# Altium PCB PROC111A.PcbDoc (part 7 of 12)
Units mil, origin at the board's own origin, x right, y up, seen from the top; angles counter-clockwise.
Board outline 7700 x 2300 mil, 6 copper layers (Top Layer, GND 1, SIG 1, SIG 2, GND 2, Bottom Layer), stack 61.062 mil thick; 841 components, 632 nets, 2914 pads, 1627 vias.
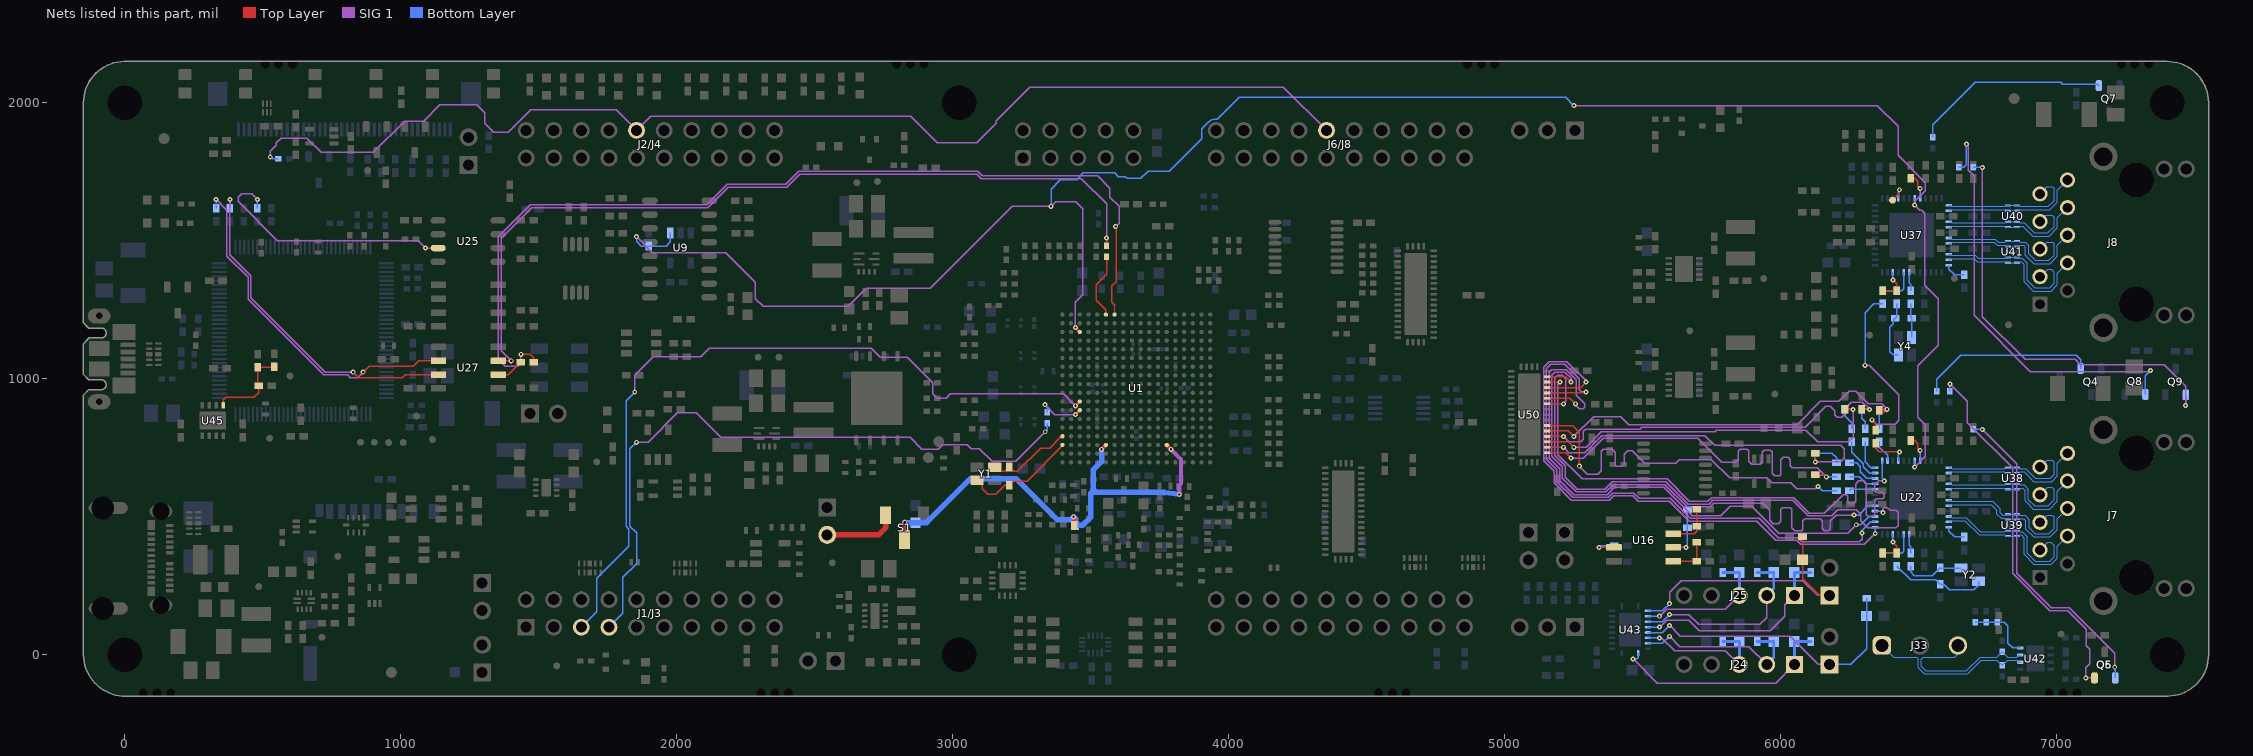
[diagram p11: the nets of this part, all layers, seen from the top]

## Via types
v1: diameter 18, hole 8, Top Layer to Bottom Layer, tented both sides, 1523 vias
v2: diameter 19.68, hole 7.87, Top Layer to Bottom Layer, tented both sides, 104 vias

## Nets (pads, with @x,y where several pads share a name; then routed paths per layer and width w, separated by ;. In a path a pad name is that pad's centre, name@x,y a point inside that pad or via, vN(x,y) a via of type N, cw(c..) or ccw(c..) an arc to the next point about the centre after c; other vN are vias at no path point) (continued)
AM263_TMS_XDS: R134.1 U25.3 | length 925.6
  Top Layer w5.3: v1(1090,1473.86) U25.3@1135.36,1473.86
  SIG 1 w4.75: v1(480.73,1650) 460.73,1670 423.12,1670 410.7,1657.58 410.7,1642.42 553.12,1500 1063.86,1500 v1(1090,1473.86)
  Bottom Layer w5.3: R134.1@480.5,1617.63 480.5,1649.77 v1(480.73,1650)
AM263_UART0_RXD: R327.1 U1.A7 | length 3465.7
  Top Layer w4: U1.A7@3586.11,1232.8 3586.11,1264.29
  Top Layer w5.3: v1(1435,1088.85) 1468.09,1088.85 1481.5,1075.45 R327.1@1481.5,1060 ; 3586.11,1264.29 3586.11,1266.7 3576.25,1276.56 3576.25,1336.51 3592.03,1352.29 3592.03,1549.64 v1(3590.08,1551.6)
  SIG 1 w4.75: v1(1435,1088.85) 1435,1057.95 1423.07,1046.02 1379.25,1046.02 1353.89,1071.38 1353.89,1514.49 1469.11,1629.71 2107.66,1629.71 2182.56,1704.61 2394.64,1704.61 2442.05,1752.02 3090.56,1752.02 3107.48,1735.1 3525.32,1735.1 3569.24,1691.18 3569.24,1658.21 3602.39,1625.06 3602.39,1563.91 v1(3590.08,1551.6)
AM263_UART0_RXD_R: R327.2 U27.2 | length 99.5
  Top Layer w5.3: U27.2@1353.27,1015.27 1389.52,1015.27 R327.2@1434.25,1060
AM263_UART0_RXD_XDS: R131.1 U27.7 | length 1225
  Top Layer w5.3: v1(827.49,1023.93) 847.33,1004.09 1005,1004.09 ; 1005,1004.4 1005.32,1004.4 1016.18,1015.27 U27.7@1136.73,1015.27
  SIG 1 w4.75: v1(380.73,1650) 380.73,1448.86 457.1,1372.49 457.1,1292.9 726.07,1023.93 v1(827.49,1023.93)
  Bottom Layer w5.3: R131.1@380.5,1617.63 380.5,1649.77 v1(380.73,1650)
AM263_UART0_TXD: R164.1 U27.3 | length 2991.7
  Top Layer w5.3: U27.3@1353.27,1065.27 v1(1400,1065.27) ; R164.1@3557,1482.17 v1(3557,1510.23)
  SIG 1 w4.75: v1(1400,1065.27) 1363.94,1101.33 1363.94,1508.94 1474.66,1619.66 2111.82,1619.66 2186.72,1694.56 2398.8,1694.56 2446.21,1741.97 3086.4,1741.97 3103.32,1725.05 3466.28,1725.05 3557,1634.33 v1(3557,1510.23)
AM263_UART0_TXD_R: R164.2 U1.A6 | length 241.4
  Top Layer w5.3: U1.A6@3554.61,1232.8 3554.61,1250.18 3519.34,1285.45 3519.34,1340.02 3558.39,1379.07 3558.39,1441.41 R164.2@3557,1442.8
AM263_UART0_TXD_XDS: R129.1 U27.6 | length 1275
  Top Layer w5.3: v1(863.7,1023.93) 885.48,1045.71 1045.71,1045.71 1065.27,1065.27 U27.6@1136.73,1065.27
  SIG 1 w4.75: v1(330.73,1650) 370.13,1610.6 370.13,1444.47 446.5,1368.1 446.5,1288.51 720.55,1014.46 721.33,1014.46 721.91,1013.88 807.81,1013.88 817.28,1004.41 844.18,1004.41 v1(863.7,1023.93)
  Bottom Layer w5.3: R129.1@330.5,1617.63 330.5,1649.77 v1(330.73,1650)
AM263_UART1_RXD: J1/J3.3 U1.L3 | length 2783.2
  Top Layer w10: v1(3444.38,902.09) U1.L3@3460.12,917.83
  SIG 1 w4.75: v1(1847.69,951.65) 1847.69,1012.66 1914.46,1079.44 2087.21,1079.44 2118.14,1110.36 2705.42,1110.36 2737.28,1078.5 2834.8,1078.5 2928.21,985.09 2928.21,945 2943.21,930 2975.39,930 2990.39,945 3401.46,945 v1(3444.38,902.09)
  Bottom Layer w5.3: J1/J3.3@1654.17,100 1710,155.83 1710,276.72 1826.8,393.51 1826.8,454.62 1816.24,465.18 1816.24,920.2 v1(1847.69,951.65)
AM263_UART1_TXD: J1/J3.4 R165.1 | length 2422
  SIG 1 w4.75: v1(1854.02,769.76) 1895.73,769.76 2002.38,876.42 2071.36,876.42 2159.83,787.95 2845.7,787.95 2888.23,745.42 2947.69,745.42 2963.32,761.06 3052.97,761.06 3066.83,747.2 3096.37,747.2 3142.87,700.7 3228.14,700.7 3255.31,727.88 3255.31,728.5 v1(3335,808.19)
  Bottom Layer w5.3: J1/J3.4@1754.17,100 1805,150.83 1805,281.22 1854.54,330.76 1854.54,441.87 1830.4,466.02 1830.4,746.14 v1(1854.02,769.76) ; v1@3335,807.6 3342.19,814.79 R165.1@3342.19,839.72
AM263_UART1_TXD_R: R165.2 U1.M3 | length 177.1
  Top Layer w10: v1(3444.38,870.59) U1.M3@3460.12,886.34
  SIG 1 w5.3: v1(3334.5,906.16) 3370.07,870.59 v1(3444.38,870.59)
  Bottom Layer w5.3: v1(3334.5,906.16) 3342.19,898.47 R165.2@3342.19,879.09
AM263_WARMRSTN: R5.2 U1.C3 U9.1 U22.43 U37.43 | length 7357.5
  Top Layer w10: v1(3444.38,1185.55) U1.C3@3460.12,1169.8
  SIG 1 w4.75: v1(1854.02,1515) 1911.65,1457.37 2177.48,1457.37 2285,1349.85 2285,1290.79 2313,1262.79 2620.94,1262.79 2685.96,1327.81 2919.1,1327.81 3216.29,1625 v1(3356.1,1625) 3372.16,1641.06 3446.17,1641.06 3470.22,1617 3470.22,1303.81 3444.38,1277.97 v1(3444.38,1185.55) ; v1(5250,1990) 6350,1990 6425,1915 6425,1810.02 6524.25,1710.77 6524.25,1682.03 6485.02,1642.8 v1(6485.02,1629.98) 6504,1611 6510.47,1611 6522.23,1599.23 6522.23,1338.26 6571.09,1289.41 6571.09,1121.92 6496.97,1047.79 6496.97,860.2 6524.25,832.92 6524.25,719.21 v1(6485.02,679.98)
  Bottom Layer w5.3: v1(1854.02,1515) 1854.02,1498.05 1871.02,1481.04 R5.2@1898.11,1481.04 1961.04,1481.04 1976.56,1496.56 U9.1@1976.56,1528.43 ; v1(3356.1,1625) 3356.1,1687.38 3390.1,1721.38 3448.34,1721.38 3472.81,1745.84 3586.02,1745.84 3598.95,1732.91 3624.33,1732.91 3631.32,1725.92 3681.74,1725.92 3707.48,1751.66 3784.31,1751.66 3902.21,1869.57 3902.21,1906.07 3927.45,1931.31 cw(c3954.19,1900.19) 3958.65,1940.98 4037.19,2019.52 5220.48,2019.52 v1(5250,1990) ; v1(6485.02,679.98) U22.43@6485.02,703.9 ; v1(6485.02,1629.98) U37.43@6485.02,1653.9
AM263_XTAL_XI: C58.1 U1.T1 Y1.1 | length 416.1
  Top Layer w5.3: Y1.1@3088.01,632.59 3092.89,632.59 3106.98,618.51 3106.98,601.63 3126.91,581.69 3155.48,581.69 3188.34,614.56 3204.72,614.56 C58.1@3205,614.84 3219.27,629.1 3269.37,629.1 3397.13,756.87 U1.T1@3397.13,760.35
AM263_XTAL_XO: C59.1 U1.R1 Y1.3 | length 317.9
  Top Layer w5.3: Y1.3@3151.99,679.84 3167.42,664.4 3188.69,664.4 C59.1@3205,680.71 3221.4,664.32 3233.73,664.32 3317.98,748.57 3350.62,748.57 3389.63,787.58 3392.86,787.58 U1.R1@3397.13,791.85
BP_PORZ: J2/J4.16 J6/J8.56 R180.2 | length 4341.6
  SIG 1 w4.75: v1(526.94,1803.36) 526.94,1824.32 549.25,1846.63 549.25,1855 566.59,1872.34 659.83,1872.34 711.41,1820.75 901.07,1820.75 1014.32,1934 1082.5,1934 1142,1993.5 1275,1993.5 1303.75,1964.75 1303.75,1926.75 1337.5,1893 1388.83,1893 1470,1974.17 1780,1974.17 J2/J4.16@1854.17,1900 1905.53,1951.36 2240,1951.36
  SIG 1 w5.3: 2240,1951.36 2847.77,1951.36 2944.28,1854.85 3087.63,1854.85 3158.06,1925.28 3158.06,1935.77 3279.01,2056.72 4197.45,2056.72 J6/J8.56@4354.17,1900
  Bottom Layer w5.3: v1(526.94,1803.36) 530.2,1803.36 536.24,1797.32 R180.2@556,1797.32
CAN_STB: R244.1 R248.1 R250.2 U42.8 | length 238
  Bottom Layer w5.3: R248.1@6705,117.87 R250.2@6745,117.87 R244.1@6785,117.87 6810,117.87 6823.16,104.71 6823.16,41.84 6840.16,24.84 U42.8@6867.68,24.84
CANA_N: J33.1 R246.2 U42.6 | length 601.7
  Bottom Layer w4.1: J33.1@6366.38,33.86 6409.77,-9.53 6492.64,-9.53 6498.72,-15.62 6498.72,-46.78 6520.48,-68.54 6676.84,-68.54 6726.39,-18.99 6783.25,-18.99 R246.2@6802.8,-38.54 6822.35,-18.99 6854.62,-18.99 6861.97,-26.34 U42.6@6867.68,-26.34
CANA_P: J33.3 R247.2 U42.7 | length 601.6
  Bottom Layer w4.1: J33.3@6641.97,33.86 6641.97,2.58 6629.86,-9.53 6516.4,-9.53 6509.62,-16.31 6509.62,-42.26 6525,-57.64 6672.33,-57.64 6721.87,-8.09 6783.25,-8.09 R247.2@6802.8,11.46 6822.35,-8.09 6854.62,-8.09 6861.97,-0.75 U42.7@6867.68,-0.75
DAC_EXT_VREF: J18.2 S1.3 | length 268.8
  Top Layer w20: J18.2@2545,434.47 2731.59,434.47 2756.71,459.58 S1.3@2756.71,506.22
DAC_VREF: C89.1 C90.1 C91.1 S1.2 U1.T6 U1.T13 | length 1749.6
  Top Layer w15: S1.2@2825.61,415.67 v1(2825.61,479.98) ; v1(3437.63,500) 3440,497.63 C91.1@3440,468.62 ; v1(3538.87,744.61) U1.T6@3554.61,760.35 ; U1.T13@3775.09,760.35 v1(3790.83,744.61)
  SIG 1 w15: v1(3790.83,744.61) 3827.15,708.29 3827.15,665.87 3827.15,620.15 3820.49,613.5 v1(3820.49,581.15)
  Bottom Layer w18: 3538.87,725.74 v1(3538.87,744.61)
  Bottom Layer w20: v1(2825.61,479.98) 2825.61,479.34 2826.45,478.5 C89.1@2865,478.5 2865,478.64 2905,478.64 3064.51,638.15 3229.55,638.15 3378.56,489.14 3426.78,489.14 v1(3437.63,500) 3445,492.63 C90.1@3445,468.53 3446.18,469.71 3470.8,469.71 3499.28,498.19 3499.28,584.65 3508.69,594.07 3508.69,669.75 3538.87,699.92 3538.87,725.74 ; 3503.16,588.54 3745.75,588.54 3765,588.18 cw(c3764.68,570.78) 3766.9,588.04 v1(3820.49,581.15)
EEPROM_A0: R318.2 R321.2 U16.1 | length 154.4
  Top Layer w5.3: U16.1@5610.08,339.14 5694.38,339.14 R318.2@5695.31,338.21 R321.2@5695.31,406.99
EEPROM_A1: R319.2 R322.2 U16.2 | length 184.1
  Top Layer w5.3: U16.2@5610.08,389.14 v1(5656.02,389.14)
  Bottom Layer w5.3: v1(5656.02,389.14) 5661.68,394.81 R322.2@5661.68,461.02 R319.2@5661.68,525
EEPROM_A2: R320.2 R323.2 U16.3 | length 167.7
  Top Layer w5.3: U16.3@5610.08,439.14 5686.53,439.14 5695.31,447.92 R323.2@5695.31,465 R320.2@5695.31,526.73
EEPROM_WP: R316.1 U16.7 | length 110.1
  Top Layer w5.3: v1(5342.11,389.14) U16.7@5395.51,389.14
  Bottom Layer w5.3: v1(5342.11,389.14) 5348.01,395.04 R316.1@5396.38,395.04
EQEP0_A: C214.1 J24.1 R236.1 U43.20 | length 828.4
  SIG 1 w4.75: v1(5465,-15) 5552.83,-102.83 5981.34,-102.83 J24.1@6049.18,-35
  Bottom Layer w5.3: v1(5465,-15) 5465.09,-14.91 5478.28,-14.91 5483.19,-10 U43.20@5483.19,5.98
  Bottom Layer w10: J24.1@6049.18,-35 C214.1@6049.18,48.5 R236.1@6109.18,48.5
EQEP0_B: C215.1 J24.2 R237.1 U43.18 | length 637.3
  SIG 1 w4.75: v1(5596.83,67) 5633.83,30 5884.18,30 J24.2@5949.18,-35
  Bottom Layer w5.3: U43.18@5518.62,41.41 5571.24,41.41 v1(5596.83,67)
  Bottom Layer w10: R237.1@5914.18,48.5 C215.1@5974.18,48.5 5974.18,-10 J24.2@5949.18,-35
EQEP0_INDEX: C216.1 J24.3 R238.1 U43.17 | length 514.2
  SIG 1 w4.75: v1(5560.83,61.1) 5563.26,58.67 5571.33,58.67 5615,15 5799.18,15 J24.3@5849.18,-35
  Bottom Layer w5.3: U43.17@5518.62,61.1 v1(5560.83,61.1)
  Bottom Layer w10: R238.1@5790,48.5 C216.1@5850,48.5 5850,-34.18 J24.3@5849.18,-35
EQEP0_STROBE: C220.1 J15.1 R242.1 U43.16 | length 1068.2
  SIG 1 w5.3: v1(5596.83,106.37) 5636.2,67 6034.58,67 6136.58,-35 J15.1@6177.06,-35
  Bottom Layer w5.3: U43.16@5518.62,80.78 5571.24,80.78 v1(5596.83,106.37) ; J15.1@6177.06,-35 6252.9,-35 6310.67,22.77 C220.1@6310.67,140.82 6311.51,141.66 R242.1@6311.51,205.53
EQEP2_A: C217.1 J25.1 R239.1 U43.15 | length 777.5
  SIG 1 w4.75: v1(5560.83,100.47) 5585.98,125.62 5666.23,125.62 5705,86.85 5961.85,86.85 6015,140 6015,180.82 J25.1@6049.18,215
  Bottom Layer w5.3: U43.15@5518.62,100.47 v1(5560.83,100.47)
  Bottom Layer w10: J25.1@6049.18,215 C217.1@6049.18,298.5 R239.1@6109.18,298.5
EQEP2_B: C218.1 J25.2 R240.1 U43.14 | length 700.2
  SIG 1 w4.75: v1(5596.83,145.74) 5666.12,145.74 5701.86,110 5924.18,110 5949.18,135 J25.2@5949.18,215
  Bottom Layer w5.3: U43.14@5518.62,120.15 5571.24,120.15 v1(5596.83,145.74)
  Bottom Layer w10: R240.1@5914.18,298.5 C218.1@5974.18,298.5 5974.18,240 J25.2@5949.18,215
EQEP2_INDEX: C219.1 J25.3 R241.1 U43.13 | length 505.8
  SIG 1 w4.75: v1(5560.83,139.84) 5586.25,165.27 5604.91,165.27 5605.18,165 5799.18,165 J25.3@5849.18,215
  Bottom Layer w5.3: U43.13@5518.62,139.84 v1(5560.83,139.84)
  Bottom Layer w10: R241.1@5790,298.5 C219.1@5850,298.5 5850,215.82 J25.3@5849.18,215
EQEP2_STROBE: C221.1 J16.1 R243.1 U43.12 | length 1026.2
  Top Layer w5.3: R243.1@6078.62,428.2 C221.1@6078.62,344.67 6078.62,276.16 6139.78,215 J16.1@6177.06,215
  SIG 1 w5.3: v1(5596.83,185.11) 5596.83,226.91 5638.61,268.7 6080,268.7 6133.7,215 J16.1@6177.06,215
  Bottom Layer w5.3: U43.12@5518.62,159.52 5571.24,159.52 v1(5596.83,185.11)
ETH1_CLKOUT: R106.2 R213.1 | length 681.7
  Top Layer w5.3: v1(6330,851.54) 6342.48,839.06 6342.48,814.89 R106.2@6343.31,814.06
  SIG 1 w5.3: v1(6305,1048.82) 6320.65,1048.82 6428.11,941.35 6428.11,849.23 6414.36,835.48 6346.06,835.48 v1(6330,851.54)
  Bottom Layer w5.3: v1(6305,1048.82) 6306.28,1050.09 6306.28,1240.04 6337.61,1271.38 R213.1@6370,1271.38
ETH1_CLKOUT_R: R106.1 U22.40 | length 143.4
  Top Layer w5.3: R106.1@6343.31,766.82 6343.31,748.47 6356.77,735 v1(6430,735)
  Bottom Layer w5.3: U22.40@6425.96,703.9 6425.96,730.96 v1(6430,735)
ETH1_GPIO_1: R114.1 R126.2 U22.22 | length 124.8
  Top Layer w5.3: R114.1@6370,368.62 R126.2@6420.85,368.62 6420.97,368.5 6420.97,393.56 v1(6406.28,408.25)
  Bottom Layer w5.3: v1(6406.28,408.25) U22.22@6406.28,436.18
ETH1_LED0: Q5.1 R227.1 | length 1377.5
  Top Layer w5.3: v1(7105,-83.58) Q5.1@7136.6,-83.58
  SIG 1 w5.3: v1(6612.73,981.46) 6675.85,918.34 6675.85,841.55 6840,677.4 6840,295.22 6974.89,160.33 7040,160.33 7107.23,93.1 7107.23,31.91 7119.52,19.62 7119.52,-32.87 7105,-47.39 v1(7105,-83.58)
  Bottom Layer w5.3: R227.1@6612.73,954.68 v1(6612.73,981.46)
ETH1_LED1: Q6.1 R229.1 | length 1171.5
  SIG 1 w5.3: v1(6730,816.71) 6855,691.71 6855,295.21 6979.28,170.92 7044.39,170.92 7210,5.32 v1(7210,-45)
  Bottom Layer w5.3: R229.1@6696.59,817.35 6729.36,817.35 v1(6730,816.71) ; v1(7210,-45) 7211.4,-46.4 Q6.1@7211.4,-83.58
ETH1_LED2: Q4.1 R225.1 | length 639.7
  Bottom Layer w5.3: R225.1@6565,954.31 6565,998.44 6651.44,1084.88 7070.44,1084.88 7086.69,1068.62 Q4.1@7086.69,1037.24
ETH1_PWDN: R305.2 U22.44 | length 96.3
  Top Layer w5.3: R305.2@6470,776.46 6485.61,776.46 6497.07,765 6497.07,747.93 v1(6505,740)
  Bottom Layer w5.3: U22.44@6504.7,703.9 6504.7,739.7 v1(6505,740)
ETH1_RBIAS: R107.2 U22.12 | length 78.8
  Bottom Layer w5.3: U22.12@6609.03,461.77 6609.03,447.39 6629.43,426.99 R107.2@6665,426.99
ETH1_RD0: R102.1 R108.1 R120.2 U50.2 | length 1556.3
  Top Layer w5.3: U50.2@5153.35,732.24 5220.31,732.24 v1(5240,712.56) ; R108.1@6124.92,652.65 6157.35,652.65 v1(6165,645)
  SIG 1 w4.75: v1(5240,712.56) 5284.78,712.56 5356.27,784.04 5699.85,784.04 5786.89,697 5834.43,697 5845,707.58 5845,737.63 5852.37,745 5877,745 5883.5,738.5 5883.5,701.74 5895.41,689.84 5925.12,689.84 5932.5,697.22 5932.5,734.31 5940,741.81 5961.9,741.81 5968.31,735.4 5968.31,657.56 5977.58,648.29 5995.75,648.29 6000.6,653.14 6000.6,707.03 6008.69,715.12 6026.31,715.12 6034.38,707.05 6034.38,685.22 6041.29,678.31 6131.69,678.31 v1(6165,645)
  Bottom Layer w5.3: R120.2@6124.92,652.65 6155.55,652.65 6163.2,645 v1(6165,645) ; v1(6165,645) v1(6165,645) ; v1(6165,645) v1(6165,645) ; v1(6165,645) R102.1@6201.89,645.04 v1(6165,645)
ETH1_RD0_R: R102.2 U22.33 | length 102.9
  Bottom Layer w5.3: R102.2@6249.14,645.04 6284.21,645.04 6310,619.25 U22.33@6341.32,619.25
ETH1_RD1: R103.1 R109.1 R121.2 U50.3 | length 1441.6
  Top Layer w5.3: U50.3@5153.35,751.93 v1(5213,751.93) ; v1(6124.92,698.96) 6125,699.04 R109.1@6125,730.96
  SIG 1 w4.75: v1(5213,751.93) 5232.25,732.68 5290.3,732.68 5351.72,794.09 5725.18,794.09 5760,759.28 6217.65,759.28 6230,746.93 6230,712.58 6216.39,698.96 v1(6124.92,698.96)
  Bottom Layer w5.3: v1(6124.92,698.96) 6125,699.04 6125,730.96 R121.2@6125.11,730.85 6185,730.85 6201.89,713.96 R103.1@6201.89,695.04
ETH1_RD1_R: R103.2 U22.34 | length 126.8
  Bottom Layer w5.3: R103.2@6249.14,695.04 6249.18,695 6275.16,695 6288.01,682.15 6288.01,662.74 6311.81,638.94 U22.34@6341.32,638.94
ETH1_RD2: R104.1 R115.1 R127.2 U50.4 | length 1405.3
  Top Layer w5.3: U50.4@5153.35,771.61 5230.31,771.61 v1(5250,751.93) ; R115.1@6233.01,889.34 6261.64,889.34 v1(6261.73,889.27)
  SIG 1 w4.75: v1(5250,751.93) 5294.28,751.93 5350,807.65 5760.18,807.65 5766.61,814.08 6090.92,814.08 6133.23,771.77 6244.93,771.77 6261.73,788.57 v1(6261.73,889.27)
  Bottom Layer w5.3: R104.1@6256.28,818.62 6256.28,840.72 6233.01,863.99 6233.01,889.35 6261.65,889.35 v1(6261.73,889.27)
ETH1_RD2_R: R104.2 U22.35 | length 159.3
  Bottom Layer w5.3: R104.2@6256.28,771.38 6256.28,733.72 6298.61,691.39 6298.61,681.98 6321.97,658.62 U22.35@6341.32,658.62
ETH1_RD3: R105.1 R116.1 R128.2 U50.5 | length 1451.1
  Top Layer w5.3: U50.5@5153.35,791.3 v1(5213,791.3) ; R116.1@6293.01,889.35 v1(6321.73,889.27) v1(6321.73,889.27)
  SIG 1 w4.75: v1(5213,791.3) 5232.52,771.77 5275,771.77 5285,781.77 5285,809.08 5293.62,817.7 5488.89,817.7 5495.32,824.13 6063.36,824.13 6087.72,824.13 6163.59,900 6179.53,900 6195,884.53 6195,869.23 6204.23,860 6220.2,860 6230,869.8 6230,890.56 6255.24,915.8 6295.2,915.8 v1(6321.73,889.27)
  Bottom Layer w5.3: R105.1@6306.28,818.62 6306.28,843.72 6293.01,856.99 R128.2@6293.01,889.35 v1(6321.73,889.27) v1(6321.73,889.27)
ETH1_RD3_R: R105.2 U22.36 | length 116.2
  Bottom Layer w5.3: R105.2@6306.28,771.38 6306.28,698.71 6326.68,678.31 U22.36@6341.32,678.31
ETH1_RX_CTL: R101.1 R113.1 R125.2 U50.6 | length 1489.3
  Top Layer w5.3: U50.6@5153.35,810.98 5230.31,810.98 v1(5250,791.3)
  Top Layer w15: R113.1@6356.28,886.06 6380.9,886.06 6384.27,889.43 6384.92,889.43 v1(6385,889.35)
  SIG 1 w4.75: v1(5250,791.3) 5321.99,863.28 5420,863.28 5449.1,834.18 5590,834.18 6059.2,834.18 6143.59,918.57 6210,918.57 6247.19,955.76 6271.29,955.76 6317.71,909.35 6365,909.35 v1(6385,889.35)
  Bottom Layer w5.3: R101.1@6356.28,818.62 R125.2@6356.28,886.06 6356.28,889.43 6384.92,889.43 v1(6385,889.35)
ETH1_RX_CTL_R: R101.2 U22.38 | length 80
  Bottom Layer w5.3: R101.2@6356.28,771.38 6356.28,752.66 6386.59,722.35 U22.38@6386.59,703.9
ETH1_RXC: R100.1 U50.7 | length 1448.9
  Top Layer w5.3: U50.7@5153.35,830.67 5245.9,830.67 5270,806.57 v1(5270,683.39)
  SIG 1 w4.75: v1(5270,683.39) 5298.39,655 5337.57,655 5349.83,667.26 5349.83,738.13 5356.7,745 5390,745 5400.88,734.12 5400.88,686.51 5405,682.4 5423.7,682.4 5432.03,690.72 5432.03,726.84 5445.19,740 5461.43,740 5507.06,694.36 5619.87,694.36 5632.78,707.27 5748.2,707.27 5814.65,640.82 5949.14,640.82 5966.71,623.25 6036.8,623.25 6058.57,601.48 6125.81,601.48 6134.33,610 v1(6135.22,610)
  Bottom Layer w5.3: v1(6135.22,610) 6150.18,595.04 R100.1@6201.89,595.04
ETH1_RXC_R: R100.2 U22.32 | length 94.1
  Bottom Layer w5.3: R100.2@6249.14,595.04 6253.66,599.57 U22.32@6341.32,599.57
ETH1_TD0: U22.28 U50.11 | length 2085.4
  Top Layer w5.3: U50.11@5153.35,909.41 v1(5213,909.41)
  SIG 1 w4.75: v1(5213,909.41) 5213,911.06 5220.75,918.81 5220.75,999.62 5207.34,1013.03 5192.66,1013.03 5180.75,1001.12 5180.75,723.2 5218.7,685.25 5218.7,643.58 5262.14,600.14 5362.16,600.14 5389.09,627.07 5583.98,627.07 5664.73,546.31 5740,546.31 5753.54,559.85 6042.9,559.85 6099.72,503.03 6183.71,503.03 6206.4,525.72 6272.97,525.72 6290,508.7 6290,485 6315,460 6416.88,460 6425,468.12 6425,516.5 6418.52,522.98 6395.99,522.98 6385.73,533.24 6375,533.24 6370.03,528.27 v1(6370,515)
  Bottom Layer w5.3: U22.28@6341.32,520.83 6364.17,520.83 v1(6370,515)
ETH1_TD1: U22.27 U50.12 | length 2090.4
  Top Layer w5.3: U50.12@5153.35,929.09 5236.14,929.09 v1(5255.83,909.41)
  SIG 1 w4.75: v1(5255.83,909.41) 5255.83,906.6 5270.19,892.24 5283.63,892.24 5290,898.61 5290,910.24 5259.52,940.71 5259.52,995.84 5222.24,1033.13 5170.28,1033.13 5160.65,1023.51 5160.65,712.02 5198.6,674.07 5198.6,631.4 5249.96,580.04 5370.49,580.04 5397.41,606.97 5575.65,606.97 5678.62,504 5782.11,504 5816.59,538.48 5894.32,538.48 5992.8,440 6242.27,440 v1(6273.51,471.24)
  Bottom Layer w5.3: v1(6273.51,471.24) 6289.75,471.24 6319.65,501.14 U22.27@6341.32,501.14
ETH1_TD2: U22.26 U50.13 | length 2086.8
  Top Layer w5.3: U50.13@5153.35,948.78 5290.96,948.78 v1(5294.69,952.5)
  SIG 1 w4.75: v1(5294.69,952.5) 5277.5,952.5 5270,960 5270,999.11 5269.57,999.54 5269.57,1000.01 5217.01,1052.57 5166.69,1052.57 5150.6,1036.48 5150.6,707.86 5188.55,669.91 5188.55,627.24 5245.8,569.99 5374.65,569.99 5390.32,585.66 5467.97,585.66 5487.22,566.41 5599.75,566.41 5672.21,493.95 5921.05,493.95 5990.7,424.3 6061.31,424.3 6075.56,410.05 6285.05,410.05 6294.47,419.47 v1(6294.47,440.85)
  Bottom Layer w5.3: v1(6294.47,440.85) 6294.47,450.71 6325.21,481.46 U22.26@6341.32,481.46
ETH1_TD3: U22.25 U50.14 | length 2087.2
  Top Layer w5.3: U50.14@5153.35,968.46 5274.41,968.46 v1(5294.69,988.73)
  SIG 1 w4.75: v1(5294.69,988.73) 5294.69,992.55 5224.62,1062.62 5161.94,1062.62 5140.55,1041.23 5140.55,703.7 5178.5,665.75 5178.5,623.07 5241.64,559.94 5378.81,559.94 5394.48,575.61 5463.81,575.61 5483.06,556.36 5595.58,556.36 5668.05,483.9 5912.5,483.9 5982.15,414.25 6057.15,414.25 6071.4,400 6302.17,400 v1(6342.17,440)
  Bottom Layer w5.3: U22.25@6341.32,461.77 6341.32,440.85 v1(6342.17,440)
ETH1_TD_A_N: J7.10 U22.2 U38.2 U38.9 | length 517.6
  Bottom Layer w4: U22.2@6609.03,658.62 6616.12,658.62 6620.11,662.61 6810.13,662.61 6814.12,658.62 U38.9@6823.14,658.62 U38.2@6856.02,658.62 6863.2,658.62 6867.19,662.61 6882.5,662.61 6917.37,627.74 6980.85,627.74 7002.19,649.09 7002.19,693.12 J7.10@7039.08,730
ETH1_TD_A_P: J7.9 U22.1 U38.1 U38.10 | length 515.8
  Bottom Layer w4: U22.1@6609.03,678.31 6616.12,678.31 6620.11,674.31 6810.13,674.31 6814.12,678.31 U38.10@6823.14,678.31 U38.1@6856.02,678.31 6863.2,678.31 6867.19,674.31 6887.35,674.31 6922.22,639.44 6976.01,639.44 6990.49,653.93 6990.49,698.4 6983.9,705 6964.08,705 J7.9@6939.08,680
ETH1_TD_B_N: J7.8 U22.5 U38.5 U38.6 | length 552
  Bottom Layer w4: U22.5@6609.03,599.57 6616.12,599.57 6620.11,603.56 6794.85,603.56 6811.96,603.56 6815.96,599.57 U38.6@6823.14,599.57 U38.5@6856.02,599.57 6863.2,599.57 6867.19,603.56 6876.59,603.56 6885,595.15 6885,557.74 6914.76,527.98 6973.79,527.98 7002.19,556.39 7002.19,593.12 J7.8@7039.08,630
ETH1_TD_B_P: J7.7 U22.4 U38.4 U38.7 | length 552.7
  Bottom Layer w4: U22.4@6609.03,619.25 6616.12,619.25 6620.11,615.26 6790,615.26 6811.96,615.26 6815.96,619.25 U38.7@6823.14,619.25 U38.4@6856.02,619.25 6863.2,619.25 6867.19,615.26 6881.44,615.26 6896.7,600 6896.7,562.59 6919.61,539.68 6968.94,539.68 6990.49,561.23 6990.49,599.07 6982.02,607.54 6966.62,607.54 J7.7@6939.08,580
ETH1_TD_C_N: J7.6 U22.8 U39.2 U39.9 | length 575.3
  Bottom Layer w4: U22.8@6609.03,540.51 6616.12,540.51 6620.11,544.5 6762.47,544.5 6783.04,523.94 6783.04,509.43 6798.47,494 6810.97,494 6815.69,489.28 U39.9@6822.87,489.28 U39.2@6855.75,489.28 6862.93,489.28 6866.92,493.28 6880,493.28 6888.3,484.98 6888.3,455.53 6916.89,426.94 6975.48,426.94 7002.19,453.65 7002.19,493.12 J7.6@7039.08,530
ETH1_TD_C_P: J7.5 U22.7 U39.1 U39.10 | length 574.1
  Bottom Layer w4: U22.7@6609.03,560.2 6616.12,560.2 6620.11,556.2 6767.32,556.2 6794.74,528.78 6794.74,514.27 6803.31,505.7 6812.42,505.7 6815.69,508.97 U39.10@6822.87,508.97 U39.1@6855.75,508.97 6862.93,508.97 6866.92,504.98 6884.85,504.98 6900,489.82 6900,460.38 6921.74,438.64 6970.64,438.64 6990.49,458.5 6990.49,499.48 6984.28,505.7 6964.78,505.7 J7.5@6939.08,480
ETH1_TD_D_N: J7.4 U22.11 U39.5 U39.6 | length 602.4
  Bottom Layer w4: U22.11@6609.03,481.46 6616.12,481.46 6620.11,485.45 6667.1,485.45 6718.33,434.22 6811.69,434.22 6815.69,430.23 U39.6@6822.87,430.23 U39.5@6855.75,430.23 6862.93,430.23 6866.92,434.22 6870.52,434.22 6881.57,423.18 6881.57,363.47 6916.99,328.05 6979.73,328.05 7002.19,350.51 7002.19,393.12 J7.4@7039.08,430
ETH1_TD_D_P: J7.3 U22.10 U39.4 U39.7 | length 602.1
  Bottom Layer w4: U22.10@6609.03,501.14 6616.12,501.14 6620.11,497.15 6671.94,497.15 6723.17,445.92 6811.69,445.92 6815.69,449.91 U39.7@6822.87,449.91 U39.4@6855.75,449.91 6862.93,449.91 6866.92,445.92 6875.37,445.92 6893.27,428.02 6893.27,368.32 6921.84,339.75 6974.88,339.75 6990.49,355.36 6990.49,396.37 6978.62,408.25 6967.33,408.25 J7.3@6939.08,380
ETH1_TX_CTL_EN: U22.37 U50.15 | length 2086.1
  Top Layer w5.3: U50.15@5153.35,988.15 v1(5200,988.15)
  SIG 1 w4.75: v1(5200,988.15) 5192.66,980.81 5192.66,725.5 5281.05,637.12 5588.14,637.12 5668.89,556.36 5735.84,556.36 5749.38,569.9 6047.07,569.9 6103.88,513.08 6157.97,513.08 6225.43,580.54 6236.38,580.54 6242.27,574.65 6242.27,554.92 6249.07,548.12 6264.84,548.12 6270.75,554.04 6270.75,618.83 6281.92,630 6300,630 6310,620 6310,508.09 6318.78,499.3 6331.42,499.3 6340.33,508.21 6340.33,558.69 6346.64,565 6368.83,565 6375,571.17 6375,580.54 6366.85,588.69 6346.65,588.69 6340.33,595 6340.33,615.33 6355,630 v1(6375,630)
  Bottom Layer w5.3: U22.37@6366.91,703.9 6366.91,639.45 6375,631.36 v1(6375,630)
ETH1_TXC: U22.29 U50.16 | length 2084.3
  Top Layer w5.3: U50.16@5153.35,1007.83 5220.31,1007.83 v1(5240,988.15)
  SIG 1 w4.75: v1(5240,988.15) 5240,1001.16 5218.07,1023.08 5180.84,1023.08 5170.7,1012.95 5170.7,719.04 5208.65,681.09 5208.65,639.42 5257.98,590.09 5366.32,590.09 5393.25,617.02 5579.81,617.02 5660.57,536.26 5744.16,536.26 5757.7,549.8 5934.38,549.8 5960,524.18 5960,487.01 5972.01,475 5991,475 6000,484 6000,526.6 6006.64,533.24 6035,533.24 6040,528.24 6040,460 6049.95,450.05 6075,450.05 6080,455.05 6080,485 6087.98,492.98 6143.59,492.98 6150,486.57 6150,457.03 6156.98,450.05 6174.29,450.05 6180,455.76 6180,485.11 6201.36,506.47 v1(6265,506.47)
  Bottom Layer w5.3: v1(6265,506.47) 6281.61,506.47 6315.64,540.51 U22.29@6341.32,540.51
ETH1_XI: R117.2 R118.2 U22.20 | length 139
  Bottom Layer w5.3: R118.2@6370,368.62 6438.54,368.62 6445.65,375.73 U22.20@6445.65,436.18
ETH1_XO: R119.2 U22.19 | length 69.5
  Bottom Layer w5.3: U22.19@6465.33,436.18 6465.33,396.87 6470,392.2 R119.2@6470,368.62
ETH1_XTAL_XI: C112.1 R117.1 Y2.1 | length 353.4
  Bottom Layer w5.3: R117.1@6420,321.38 6470,271.38 6562.13,271.38 C112.1@6578.01,255.5 6590.49,255.5 6610.49,235.5 6699.35,235.5 6716.59,252.74 Y2.1@6716.59,266.88
ETH1_XTAL_XO: C113.1 R119.1 Y2.3 | length 221.6
  Bottom Layer w5.3: R119.1@6470,321.38 6470,300.76 6484.18,286.58 6549.09,286.58 C113.1@6578.01,315.5 6579.39,314.12 Y2.3@6652.61,314.12
ETH2_CLKOUT: TP20.1 U37.40 | length 81
  Top Layer w5.3: TP20.1@6405,1647.09 6429.77,1671.86 6429.77,1684.77 v1(6430,1685)
  Bottom Layer w5.3: U37.40@6425.96,1653.9 6425.96,1680.96 v1(6430,1685)
ETH2_GPIO_1: R209.1 R221.2 U37.22 | length 124.8
  Top Layer w5.3: R209.1@6370,1318.62 6420.85,1318.62 R221.2@6420.97,1318.5 6420.97,1343.56 v1(6406.28,1358.25)
  Bottom Layer w5.3: v1(6406.28,1358.25) U37.22@6406.28,1386.18
ETH2_LED0: Q8.1 R233.1 | length 1557.5
  SIG 1 w4.75: v1(6672.8,1850) 6678.75,1844.05 6678.75,1756.25 6700,1735 6700,1230 6903.58,1026.42 7330.55,1026.42 7331.69,1027.57 7337.57,1027.57 v1(7340,1030)
  Bottom Layer w5.3: R233.1@6645,1766.06 6663.2,1766.06 6672.14,1775 6672.14,1849.34 v1(6672.8,1850) ; Q8.1@7321.27,943.42 7321.27,1011.27 v1(7340,1030)
ETH2_LED1: Q9.1 R235.1 | length 1522.4
  SIG 1 w4.75: v1(6730,1766.06) 6730,1225 6885,1070 7066.02,1070 7085.23,1050.79 7389.21,1050.79 7466.46,973.54 v1(7466.46,903.72)
  Bottom Layer w5.3: R235.1@6698,1766.06 v1(6730,1766.06) ; v1(7466.46,903.72) 7467.73,905 Q9.1@7467.73,942.15
ETH2_LED2: Q7.1 R231.1 | length 717.7
  Bottom Layer w5.3: R231.1@6550,1874.37 6550,1920 6705,2075 7014.51,2075 7021.6,2067.92 7146.93,2067.92 Q7.1@7152.6,2062.24
ETH2_PWDN: R306.2 U37.44 | length 96.3
  Top Layer w5.3: R306.2@6470,1726.46 6485.61,1726.46 6497.07,1715 6497.07,1697.93 v1(6505,1690)
  Bottom Layer w5.3: U37.44@6504.7,1653.9 6504.7,1689.7 v1(6505,1690)
ETH2_RBIAS: R202.2 U37.12 | length 78.8
  Bottom Layer w5.3: U37.12@6609.03,1411.77 6609.03,1397.39 6629.43,1376.99 R202.2@6665,1376.99
ETH2_TD_A_N: J8.10 U37.2 U40.2 U40.9 | length 504.6
  Bottom Layer w4: U37.2@6609.03,1608.62 6616.12,1608.62 6620.11,1612.61 6787.42,1612.61 6811.96,1612.61 6815.96,1608.62 U40.9@6823.14,1608.62 U40.2@6856.02,1608.62 6863.2,1608.62 6867.19,1612.61 6974.55,1612.61 7002.19,1640.26 7002.19,1683.12 J8.10@7039.08,1720
ETH2_TD_A_P: J8.9 U37.1 U40.1 U40.10 | length 503.5
  Bottom Layer w4: U37.1@6609.03,1628.31 6616.12,1628.31 6620.11,1624.31 6782.57,1624.31 6811.96,1624.31 6815.96,1628.31 U40.10@6823.14,1628.31 U40.1@6856.02,1628.31 6863.2,1628.31 6867.19,1624.31 6969.71,1624.31 6990.49,1645.1 6990.49,1689.51 6985,1695 6964.08,1695 J8.9@6939.08,1670
ETH2_TD_B_N: J8.8 U37.5 U40.5 U40.6 | length 514.4
  Bottom Layer w4: U37.5@6609.03,1549.57 6616.12,1549.57 6620.11,1553.56 6806.02,1553.56 6811.96,1553.56 6815.96,1549.57 U40.6@6823.14,1549.57 U40.5@6856.02,1549.57 6863.2,1549.57 6867.19,1553.56 6876.57,1553.56 6913.24,1516.89 6972.7,1516.89 7002.19,1546.39 7002.19,1583.12 J8.8@7039.08,1620
ETH2_TD_B_P: J8.7 U37.4 U40.4 U40.7 | length 514.2
  Bottom Layer w4: U37.4@6609.03,1569.25 6616.12,1569.25 6620.11,1565.26 6801.17,1565.26 6811.96,1565.26 6815.96,1569.25 U40.7@6823.14,1569.25 U40.4@6856.02,1569.25 6863.2,1569.25 6867.19,1565.26 6881.41,1565.26 6918.09,1528.59 6967.85,1528.59 6990.49,1551.23 6990.49,1584.84 6982.92,1592.41 6951.74,1592.41 6939.08,1579.76 J8.7@6939.08,1570
ETH2_TD_C_N: J8.6 U37.8 U41.2 U41.9 | length 549.4
  Bottom Layer w4: U37.8@6609.03,1490.51 6616.12,1490.51 6620.11,1494.5 6772.46,1494.5 6783.69,1483.28 6811.69,1483.28 6815.69,1479.28 U41.9@6822.87,1479.28 U41.2@6855.75,1479.28 6862.93,1479.28 6866.92,1483.28 6880,1483.28 6886.53,1476.75 6886.53,1447.66 6916.56,1417.62 6976.17,1417.62 7002.19,1443.65 7002.19,1483.12 J8.6@7039.08,1520
ETH2_TD_C_P: J8.5 U37.7 U41.1 U41.10 | length 548
  Bottom Layer w4: U37.7@6609.03,1510.2 6616.12,1510.2 6620.11,1506.2 6777.31,1506.2 6788.54,1494.98 6811.69,1494.98 6815.69,1498.97 U41.10@6822.87,1498.97 U41.1@6855.75,1498.97 6862.93,1498.97 6866.92,1494.98 6884.85,1494.98 6898.23,1481.6 6898.23,1452.51 6921.41,1429.32 6971.32,1429.32 6990.49,1448.5 6990.49,1489.01 6984.5,1495 6964.08,1495 J8.5@6939.08,1470
ETH2_TD_D_N: J8.4 U37.11 U41.5 U41.6 | length 586.8
  Bottom Layer w4: U37.11@6609.03,1431.46 6616.12,1431.46 6620.11,1435.45 6700,1435.45 6711.23,1424.22 6811.69,1424.22 6815.69,1420.23 U41.6@6822.87,1420.23 U41.5@6855.75,1420.23 6862.93,1420.23 6866.92,1424.22 6870.52,1424.22 6881.57,1413.18 6881.57,1351.79 6915.31,1318.05 6979.73,1318.05 7002.19,1340.51 7002.19,1383.12 J8.4@7039.08,1420
ETH2_TD_D_P: J8.3 U37.10 U41.4 U41.7 | length 586
  Bottom Layer w4: U37.10@6609.03,1451.14 6616.12,1451.14 6620.11,1447.15 6704.85,1447.15 6716.07,1435.92 6811.69,1435.92 6815.69,1439.91 U41.7@6822.87,1439.91 U41.4@6855.75,1439.91 6862.93,1439.91 6866.92,1435.92 6875.37,1435.92 6893.27,1418.02 6893.27,1356.63 6920.16,1329.75 6974.88,1329.75 6990.49,1345.36 6990.49,1386.72 6979.83,1397.39 6966.46,1397.39 J8.3@6939.08,1370
ETH2_XI: R212.2 R213.2 U37.20 | length 139
  Bottom Layer w5.3: R213.2@6370,1318.62 R212.2@6420,1318.62 6438.54,1318.62 6445.65,1325.73 U37.20@6445.65,1386.18
ETH2_XO: R214.2 U37.19 | length 69.5
  Bottom Layer w5.3: U37.19@6465.33,1386.18 6465.33,1346.87 6470,1342.2 R214.2@6470,1318.62
ETH2_XTAL_XI: C189.1 R212.1 Y4.1 | length 219.5
  Bottom Layer w5.3: R212.1@6420,1271.38 6420,1225 C189.1@6415,1220 6407.39,1212.39 6407.39,1200 6395,1187.61 6395,1098.66 6407.24,1086.42 Y4.1@6426.38,1086.42
ETH2_XTAL_XO: C190.1 R214.1 Y4.3 | length 123.6
  Bottom Layer w5.3: R214.1@6470,1271.38 6470,1225 C190.1@6475,1220 6475,1151.78 Y4.3@6473.62,1150.4
FB_VDD_XDS3V3: C228.2 R251.1 R252.2 U45.5 | length 312.9
  Top Layer w5.3: U45.5@357.08,903.44 357.08,924.16 365.69,932.78 467.61,932.78 485.03,950.19 C228.2@485.03,974.76 481.97,977.82 R251.1@481.97,1041.61 540.03,1041.61 R252.2@541.97,1043.54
